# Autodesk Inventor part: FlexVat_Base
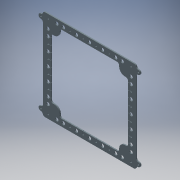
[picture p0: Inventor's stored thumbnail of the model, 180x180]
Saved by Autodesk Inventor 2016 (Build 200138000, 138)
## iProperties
Created: 2015-11
Part Number: FlexVat_Base
Material: Generic
Document SubType Name: Modeling
Designer: John
Density: 1 g/cm^3
Appearance: Default
Author: John
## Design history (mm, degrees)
feature "Base1"
node "Direct Edit1"
node "Direct Edit2"
fillet "Fillet1" dims "d24" = 5
sketch "Sketch1"
  geometry: L1 (-31.388, 174.618)-(-31.888, 174.618) reference; L2 (-31.388, -11.918)-(-31.888, -11.918) reference; L3 (-199.618, 156.308)-(-199.618, 155.81) reference; L4 (-199.618, 6.39)-(-199.618, 6.892) reference; L5 (-13.082, 6.392)-(-13.082, 6.892) reference; L6 (-180.808, 174.618)-(-181.308, 174.618) reference; L7 (-183.37, 169.575)-(-166.366, 169.575) reference; L8 (-166.366, 169.575)-(-166.366, 172.608) reference; L9 (-165.866, 172.608)-(-165.866, 169.575) reference; L10 (-165.866, 169.575)-(-151.424, 169.575) reference; L11 (-151.424, 169.575)-(-151.424, 174.618) reference; L12 (-150.924, 174.618)-(-150.924, 169.575) reference; L13 (-150.924, 169.575)-(-136.482, 169.575) reference; L14 (-136.482, 169.575)-(-136.482, 172.608) reference; L15 (-135.982, 172.608)-(-135.982, 169.575) reference; L16 (-135.982, 169.575)-(-121.54, 169.575) reference; L17 (-121.54, 169.575)-(-121.54, 174.618) reference; L18 (-121.04, 174.618)-(-121.04, 169.575) reference; L19 (-121.04, 169.575)-(-106.598, 169.575) reference; L20 (-106.598, 169.575)-(-106.598, 172.608) reference; L21 (-106.098, 172.608)-(-106.098, 169.575) reference; L22 (-106.098, 169.575)-(-91.656, 169.575) reference; L23 (-91.656, 169.575)-(-91.656, 174.618) reference; L24 (-91.156, 174.618)-(-91.156, 169.575) reference; L25 (-91.156, 169.575)-(-76.714, 169.575) reference; L26 (-76.714, 169.575)-(-76.714, 172.608) reference; L27 (-76.214, 172.608)-(-76.214, 169.575) reference; L28 (-76.214, 169.575)-(-61.772, 169.575) reference; L29 (-61.772, 169.575)-(-61.772, 174.618) reference; L30 (-61.272, 174.618)-(-61.272, 169.575) reference; L31 (-61.272, 169.575)-(-46.83, 169.575) reference; L32 (-46.83, 169.575)-(-46.83, 172.608) reference; L33 (-46.33, 172.608)-(-46.33, 169.575) reference; L34 (-46.33, 169.575)-(-29.33, 169.575) reference; L35 (-23.125, 154.794)-(-23.125, 141.366) reference; L36 (-23.125, 141.366)-(-15.092, 141.366) reference; L37 (-15.092, 140.87)-(-23.125, 140.87) reference; L38 (-23.125, 140.87)-(-23.125, 126.428) reference; L39 (-23.125, 126.428)-(-13.082, 126.428) reference; L40 (-13.082, 125.928)-(-23.125, 125.928) reference; L41 (-23.125, 125.928)-(-23.125, 111.482) reference; L42 (-15.092, 111.482)-(-23.125, 111.482) reference; L43 (-23.125, 110.986)-(-15.092, 110.986) reference; L44 (-23.125, 110.986)-(-23.125, 96.54) reference; L45 (-23.125, 96.54)-(-13.083, 96.54) reference; L46 (-13.081, 96.04)-(-23.125, 96.04) reference; L47 (-23.125, 96.04)-(-23.125, 81.602) reference; L48 (-23.125, 81.602)-(-15.092, 81.602) reference; L49 (-15.091, 81.098)-(-23.125, 81.098) reference; L50 (-23.125, 81.098)-(-23.125, 66.66) reference; L51 (-23.125, 66.66)-(-13.081, 66.66) reference; L52 (-13.082, 66.156)-(-23.125, 66.156) reference; L53 (-23.125, 66.156)-(-23.125, 51.718) reference; L54 (-15.091, 51.718)-(-23.125, 51.718) reference; L55 (-23.125, 51.214)-(-15.092, 51.214) reference; L56 (-23.125, 51.214)-(-23.125, 36.776) reference; L57 (-23.125, 36.776)-(-13.082, 36.776) reference; L58 (-13.082, 36.276)-(-23.125, 36.276) reference; L59 (-23.125, 36.276)-(-23.125, 21.834) reference; L60 (-15.092, 21.834)-(-23.125, 21.834) reference; L61 (-23.125, 21.33)-(-15.091, 21.33) reference; L62 (-23.125, 21.33)-(-23.125, 7.906) reference; L63 (-29.33, -6.875)-(-46.33, -6.875) reference; L64 (-46.33, -9.908)-(-46.33, -6.875) reference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; C1 r 1.75 at (-201, 176) reference; C2 r 1.75 at (-11.7, 171) reference; C3 r 1.75 at (-11.7, -13.3) reference; C4 r 1.75 at (-201, -13.3) reference; C5 r 1.75 at (-217.7, -10) reference; C6 r 1.75 at (-217.7, 172.7) reference; C7 r 1.75 at (5, 172.7) reference; C8 r 1.75 at (5, -10) reference; C9 r 8.125 at (-187.7, 0); C10 r 8.125 at (-187.7, 162.7); C11 r 8.125 at (-25, 162.7); C12 r 13.428 at (-25, 0); C13 r 13.428 at (-25, 162.7); C14 r 13.428 at (-187.7, 162.7); C15 r 13.428 at (-187.7, 0); A1 r 1.75 centre (-31.638, 176.35) between (-31.388, 174.618) and (-31.888, 174.618) reference; A2 r 1.75 centre (-31.638, -13.65) between (-31.888, -11.918) and (-31.388, -11.918) reference; A3 r 1.75 centre (-201.35, 156.058) between (-199.618, 156.308) and (-199.618, 155.81) reference; A4 r 1.75 centre (-201.35, 6.642) between (-199.618, 6.892) and (-199.618, 6.39) reference; A5 r 1.75 centre (-11.35, 6.642) between (-13.082, 6.392) and (-13.082, 6.892) reference; A6 r 1.75 centre (-181.058, 176.35) between (-180.808, 174.618) and (-181.308, 174.618) reference; A7 r 8.125 centre (-187.7, 162.7) between (-189.575, 154.794) and (-183.37, 169.575) reference; A8 r 3.75 centre (-166.116, 176.35) between (-165.866, 172.608) and (-166.366, 172.608) reference; A9 r 1.75 centre (-151.174, 176.35) between (-150.924, 174.618) and (-151.424, 174.618) reference; A10 r 3.75 centre (-136.232, 176.35) between (-135.982, 172.608) and (-136.482, 172.608) reference; A11 r 1.75 centre (-121.29, 176.35) between (-121.04, 174.618) and (-121.54, 174.618) reference; A12 r 3.75 centre (-106.348, 176.35) between (-106.098, 172.608) and (-106.598, 172.608) reference; A13 r 1.75 centre (-91.406, 176.35) between (-91.156, 174.618) and (-91.656, 174.618) reference; A14 r 3.75 centre (-76.464, 176.35) between (-76.214, 172.608) and (-76.714, 172.608) reference; A15 r 1.75 centre (-61.522, 176.35) between (-61.272, 174.618) and (-61.772, 174.618) reference; A16 r 3.75 centre (-46.58, 176.35) between (-46.33, 172.608) and (-46.83, 172.608) reference; A17 r 8.125 centre (-25, 162.7) between (-29.33, 169.575) and (-23.125, 154.794) reference; A18 r 3.75 centre (-11.35, 141.12) between (-15.092, 140.87) and (-15.092, 141.366) reference; A19 r 1.75 centre (-11.35, 126.178) between (-13.082, 125.928) and (-13.082, 126.428) reference; A20 r 3.75 centre (-11.35, 111.236) between (-15.092, 110.986) and (-15.092, 111.482) reference; A21 r 1.75 centre (-11.35, 96.294) between (-13.081, 96.04) and (-13.083, 96.54) reference; A22 r 3.75 centre (-11.35, 81.352) between (-15.091, 81.098) and (-15.092, 81.602) reference; A23 r 1.75 centre (-11.35, 66.406) between (-13.082, 66.156) and (-13.081, 66.66) reference; A24 r 3.75 centre (-11.35, 51.464) between (-15.092, 51.214) and (-15.091, 51.718) reference; A25 r 1.75 centre (-11.35, 36.526) between (-13.082, 36.276) and (-13.082, 36.776) reference; A26 r 3.75 centre (-11.35, 21.584) between (-15.091, 21.33) and (-15.092, 21.834) reference; A27 r 8.125 centre (-25, 0) between (-23.125, 7.906) and (-29.33, -6.875) reference; A28 r 3.75 centre (-46.58, -13.65) between (-46.83, -9.908) and (-46.33, -9.908) reference; A29 r 1.75 centre (-61.522, -13.65) between (-61.772, -11.918) and (-61.272, -11.918) reference; A30 r 3.75 centre (-76.464, -13.65) between (-76.714, -9.908) and (-76.214, -9.908) reference; A31 r 1.75 centre (-91.406, -13.65) between (-91.656, -11.918) and (-91.156, -11.918) reference; A32 r 3.75 centre (-106.348, -13.65) between (-106.598, -9.908) and (-106.098, -9.908) reference; A33 r 1.75 centre (-121.29, -13.65) between (-121.54, -11.918) and (-121.04, -11.918) reference; A34 r 3.75 centre (-136.232, -13.65) between (-136.482, -9.908) and (-135.982, -9.908) reference; A35 r 1.75 centre (-151.174, -13.65) between (-151.424, -11.918) and (-150.924, -11.918) reference; A36 r 3.75 centre (-166.116, -13.65) between (-166.366, -9.908) and (-165.866, -9.908) reference; A37 r 8.125 centre (-187.7, 0) between (-183.37, -6.875) and (-189.575, 7.906) reference; A38 r 3.75 centre (-201.35, 21.584) between (-197.608, 21.834) and (-197.609, 21.33) reference; A39 r 1.75 centre (-201.35, 36.522) between (-199.618, 36.772) and (-199.618, 36.272) reference; A40 r 3.75 centre (-201.35, 51.464) between (-197.609, 51.718) and (-197.608, 51.214) reference; A41 r 1.75 centre (-201.35, 66.406) between (-199.619, 66.66) and (-199.618, 66.156) reference; A42 r 3.75 centre (-201.35, 81.352) between (-197.608, 81.598) and (-197.609, 81.098) reference; A43 r 1.75 centre (-201.35, 96.29) between (-199.619, 96.544) and (-199.618, 96.04) reference; A44 r 3.75 centre (-201.35, 111.236) between (-197.608, 111.486) and (-197.609, 110.982) reference; A45 r 1.75 centre (-201.35, 126.178) between (-199.617, 126.424) and (-199.619, 125.924) reference; A46 r 3.75 centre (-201.35, 141.12) between (-197.608, 141.37) and (-197.609, 140.866) reference; A47 r 1.75 centre (-11.35, 156.058) between (-13.082, 155.809) and (-13.082, 156.308) reference; A48 r 1.75 centre (-181.058, -13.65) between (-181.308, -11.918) and (-180.808, -11.918) reference; A49 r 5 centre (-208.018, -17.5) between (-212.859, -18.75) and (-208.018, -22.5) reference; A50 r 5 centre (-4.682, -17.5) between (-4.682, -22.5) and (0.159, -18.75) reference; A51 r 5 centre (5, -20) between (5, -15) and (0.159, -18.75) reference; A52 r 5 centre (5, -10) between (5, -15) and (5, -5) reference; A53 r 5 centre (5, 0) between (0, 0) and (5, -5) reference; A54 r 5 centre (5, 162.7) between (5, 167.7) and (0, 162.7) reference; A55 r 5 centre (5, 172.7) between (5, 167.7) and (5, 177.7) reference; A56 r 5 centre (5, 182.7) between (0.159, 181.45) and (5, 177.7) reference; A57 r 5 centre (-4.682, 180.2) between (0.159, 181.45) and (-4.682, 185.2) reference; A58 r 5 centre (-208.018, 180.2) between (-208.018, 185.2) and (-212.859, 181.45) reference; A59 r 5 centre (-217.7, 182.7) between (-217.7, 177.7) and (-212.859, 181.45) reference; A60 r 5 centre (-217.7, 172.7) between (-217.7, 177.7) and (-217.7, 167.7) reference; A61 r 5 centre (-217.7, 162.7) between (-212.7, 162.7) and (-217.7, 167.7) reference; A62 r 5 centre (-217.7, 0) between (-217.7, -5) and (-212.7, 0) reference; A63 r 5 centre (-217.7, -10) between (-217.7, -5) and (-217.7, -15) reference; A64 r 5 centre (-217.7, -20) between (-212.859, -18.75) and (-217.7, -15) reference; 1 further point
  constraints: 7 centre point, 6 equal radius, 4 coincident, 1 tangent, 3 other
extrude "Extrusion1" join sketch "Sketch1" stored distance "d25" = 10; taper "d26" = 0 deg
sketch "Sketch2"
  geometry: L1 (-31.388, -11.918)-(-31.888, -11.918) reference; L2 (-4.682, -22.5)-(-208.018, -22.5) reference; L3 (0, 0)-(0, 162.7) reference; L4 (-208.018, 185.2)-(-4.682, 185.2) reference; L5 (-212.7, 0)-(-212.7, 162.7) reference; L6 (-180.808, -11.918)-(-181.308, -11.918) reference; L7 (-13.082, 155.809)-(-13.082, 156.308) reference; L8 (-180.808, 174.618)-(-181.308, 174.618) reference; L9 (-13.082, 6.392)-(-13.082, 6.892) reference; L10 (-199.618, 6.39)-(-199.618, 6.892) reference; L11 (-199.618, 156.308)-(-199.618, 155.81) reference; L12 (-31.388, 174.618)-(-31.888, 174.618) reference; L13 (-189.575, 13.297)-(-189.575, 21.33) reference; L14 (-197.609, 21.33)-(-189.575, 21.33) reference; L15 (-189.575, 21.834)-(-197.608, 21.834) reference; L16 (-189.575, 21.834)-(-189.575, 36.272) reference; L17 (-189.575, 36.272)-(-199.618, 36.272) reference; L18 (-199.618, 36.772)-(-189.575, 36.772) reference; L19 (-189.575, 36.772)-(-189.575, 51.214) reference; L20 (-189.575, 51.214)-(-197.608, 51.214) reference; L21 (-197.609, 51.718)-(-189.575, 51.718) reference; L22 (-189.575, 51.718)-(-189.575, 66.156) reference; L23 (-189.575, 66.156)-(-199.618, 66.156) reference; L24 (-199.619, 66.66)-(-189.575, 66.66) reference; L25 (-189.575, 66.66)-(-189.575, 81.098) reference; L26 (-197.609, 81.098)-(-189.575, 81.098) reference; L27 (-189.575, 81.598)-(-197.608, 81.598) reference; L28 (-189.575, 81.598)-(-189.575, 96.04) reference; L29 (-189.575, 96.04)-(-199.618, 96.04) reference; L30 (-199.619, 96.544)-(-189.575, 96.544) reference; L31 (-189.575, 96.544)-(-189.575, 110.982) reference; L32 (-197.609, 110.982)-(-189.575, 110.982) reference; L33 (-189.575, 111.486)-(-197.608, 111.486) reference; L34 (-189.575, 111.486)-(-189.575, 125.924) reference; L35 (-199.619, 125.924)-(-189.575, 125.924) reference; L36 (-189.575, 126.424)-(-199.617, 126.424) reference; L37 (-189.575, 126.424)-(-189.575, 140.866) reference; L38 (-197.609, 140.866)-(-189.575, 140.866) reference; L39 (-189.575, 141.37)-(-197.608, 141.37) reference; L40 (-189.575, 141.37)-(-189.575, 149.403) reference; L41 (-176.165, 169.575)-(-166.366, 169.575) reference; L42 (-166.366, 169.575)-(-166.366, 172.608) reference; L43 (-165.866, 172.608)-(-165.866, 169.575) reference; L44 (-165.866, 169.575)-(-151.424, 169.575) reference; L45 (-151.424, 169.575)-(-151.424, 174.618) reference; L46 (-150.924, 174.618)-(-150.924, 169.575) reference; L47 (-150.924, 169.575)-(-136.482, 169.575) reference; L48 (-136.482, 169.575)-(-136.482, 172.608) reference; L49 (-135.982, 172.608)-(-135.982, 169.575) reference; L50 (-135.982, 169.575)-(-121.54, 169.575) reference; L51 (-121.54, 169.575)-(-121.54, 174.618) reference; L52 (-121.04, 174.618)-(-121.04, 169.575) reference; L53 (-121.04, 169.575)-(-106.598, 169.575) reference; L54 (-106.598, 169.575)-(-106.598, 172.608) reference; L55 (-106.098, 172.608)-(-106.098, 169.575) reference; L56 (-106.098, 169.575)-(-91.656, 169.575) reference; L57 (-91.656, 169.575)-(-91.656, 174.618) reference; L58 (-91.156, 174.618)-(-91.156, 169.575) reference; L59 (-91.156, 169.575)-(-76.714, 169.575) reference; L60 (-76.714, 169.575)-(-76.714, 172.608) reference; L61 (-76.214, 172.608)-(-76.214, 169.575) reference; L62 (-76.214, 169.575)-(-61.772, 169.575) reference; L63 (-61.772, 169.575)-(-61.772, 174.618) reference; L64 (-61.272, 174.618)-(-61.272, 169.575) reference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; C1 r 1.75 at (5, -10) reference; C2 r 1.75 at (5, 172.7) reference; C3 r 1.75 at (-217.7, 172.7) reference; C4 r 1.75 at (-217.7, -10) reference; C5 r 1.75 at (-201, -13.3) reference; C6 r 1.75 at (-11.7, -13.3) reference; C7 r 1.75 at (-11.7, 171) reference; C8 r 1.75 at (-201, 176) reference; C9 r 3.75 at (-181.058, -13.65); C10 r 3.75 at (-201.35, 6.642); C11 r 3.75 at (-201.35, 156.058); C12 r 3.75 at (-181.058, 176.35); C13 r 3.75 at (-31.638, 176.35); C14 r 3.75 at (-11.35, 156.058); C15 r 3.75 at (-31.638, -13.65); C16 r 3.75 at (-11.35, 6.642); A1 r 1.75 centre (-31.638, -13.65) between (-31.888, -11.918) and (-31.388, -11.918) reference; A2 r 5 centre (-208.018, -17.5) between (-212.859, -18.75) and (-208.018, -22.5) reference; A3 r 5 centre (-4.682, -17.5) between (-4.682, -22.5) and (0.159, -18.75) reference; A4 r 5 centre (5, -20) between (5, -15) and (0.159, -18.75) reference; A5 r 5 centre (5, -10) between (5, -15) and (5, -5) reference; A6 r 5 centre (5, 0) between (0, 0) and (5, -5) reference; A7 r 5 centre (5, 162.7) between (5, 167.7) and (0, 162.7) reference; A8 r 5 centre (5, 172.7) between (5, 167.7) and (5, 177.7) reference; A9 r 5 centre (5, 182.7) between (0.159, 181.45) and (5, 177.7) reference; A10 r 5 centre (-4.682, 180.2) between (0.159, 181.45) and (-4.682, 185.2) reference; A11 r 5 centre (-208.018, 180.2) between (-208.018, 185.2) and (-212.859, 181.45) reference; A12 r 5 centre (-217.7, 182.7) between (-217.7, 177.7) and (-212.859, 181.45) reference; A13 r 5 centre (-217.7, 172.7) between (-217.7, 177.7) and (-217.7, 167.7) reference; A14 r 5 centre (-217.7, 162.7) between (-212.7, 162.7) and (-217.7, 167.7) reference; A15 r 5 centre (-217.7, 0) between (-217.7, -5) and (-212.7, 0) reference; A16 r 5 centre (-217.7, -10) between (-217.7, -5) and (-217.7, -15) reference; A17 r 5 centre (-217.7, -20) between (-212.859, -18.75) and (-217.7, -15) reference; A18 r 1.75 centre (-181.058, -13.65) between (-181.308, -11.918) and (-180.808, -11.918) reference; A19 r 1.75 centre (-11.35, 156.058) between (-13.082, 155.809) and (-13.082, 156.308) reference; A20 r 1.75 centre (-181.058, 176.35) between (-180.808, 174.618) and (-181.308, 174.618) reference; A21 r 1.75 centre (-11.35, 6.642) between (-13.082, 6.392) and (-13.082, 6.892) reference; A22 r 1.75 centre (-201.35, 6.642) between (-199.618, 6.892) and (-199.618, 6.39) reference; A23 r 1.75 centre (-201.35, 156.058) between (-199.618, 156.308) and (-199.618, 155.81) reference; A24 r 1.75 centre (-31.638, 176.35) between (-31.388, 174.618) and (-31.888, 174.618) reference; A25 r 13.428 centre (-187.7, 0) between (-176.165, -6.875) and (-189.575, 13.297) reference; A26 r 3.75 centre (-201.35, 21.584) between (-197.608, 21.834) and (-197.609, 21.33) reference; A27 r 1.75 centre (-201.35, 36.522) between (-199.618, 36.772) and (-199.618, 36.272) reference; A28 r 3.75 centre (-201.35, 51.464) between (-197.609, 51.718) and (-197.608, 51.214) reference; A29 r 1.75 centre (-201.35, 66.406) between (-199.619, 66.66) and (-199.618, 66.156) reference; A30 r 3.75 centre (-201.35, 81.352) between (-197.608, 81.598) and (-197.609, 81.098) reference; A31 r 1.75 centre (-201.35, 96.29) between (-199.619, 96.544) and (-199.618, 96.04) reference; A32 r 3.75 centre (-201.35, 111.236) between (-197.608, 111.486) and (-197.609, 110.982) reference; A33 r 1.75 centre (-201.35, 126.178) between (-199.617, 126.424) and (-199.619, 125.924) reference; A34 r 3.75 centre (-201.35, 141.12) between (-197.608, 141.37) and (-197.609, 140.866) reference; A35 r 13.428 centre (-187.7, 162.7) between (-189.575, 149.403) and (-176.165, 169.575) reference; A36 r 3.75 centre (-166.116, 176.35) between (-165.866, 172.608) and (-166.366, 172.608) reference; A37 r 1.75 centre (-151.174, 176.35) between (-150.924, 174.618) and (-151.424, 174.618) reference; A38 r 3.75 centre (-136.232, 176.35) between (-135.982, 172.608) and (-136.482, 172.608) reference; A39 r 1.75 centre (-121.29, 176.35) between (-121.04, 174.618) and (-121.54, 174.618) reference; A40 r 3.75 centre (-106.348, 176.35) between (-106.098, 172.608) and (-106.598, 172.608) reference; A41 r 1.75 centre (-91.406, 176.35) between (-91.156, 174.618) and (-91.656, 174.618) reference; A42 r 3.75 centre (-76.464, 176.35) between (-76.214, 172.608) and (-76.714, 172.608) reference; A43 r 1.75 centre (-61.522, 176.35) between (-61.272, 174.618) and (-61.772, 174.618) reference; A44 r 3.75 centre (-46.58, 176.35) between (-46.33, 172.608) and (-46.83, 172.608) reference; A45 r 13.428 centre (-25, 162.7) between (-36.535, 169.575) and (-23.125, 149.403) reference; A46 r 3.75 centre (-11.35, 141.12) between (-15.092, 140.87) and (-15.092, 141.366) reference; A47 r 1.75 centre (-11.35, 126.178) between (-13.082, 125.928) and (-13.082, 126.428) reference; A48 r 3.75 centre (-11.35, 111.236) between (-15.092, 110.986) and (-15.092, 111.482) reference; A49 r 1.75 centre (-11.35, 96.294) between (-13.081, 96.04) and (-13.083, 96.54) reference; A50 r 3.75 centre (-11.35, 81.352) between (-15.091, 81.098) and (-15.092, 81.602) reference; A51 r 1.75 centre (-11.35, 66.406) between (-13.082, 66.156) and (-13.081, 66.66) reference; A52 r 3.75 centre (-11.35, 51.464) between (-15.092, 51.214) and (-15.091, 51.718) reference; A53 r 1.75 centre (-11.35, 36.526) between (-13.082, 36.276) and (-13.082, 36.776) reference; A54 r 3.75 centre (-11.35, 21.584) between (-15.091, 21.33) and (-15.092, 21.834) reference; A55 r 13.428 centre (-25, 0) between (-23.125, 13.297) and (-36.535, -6.875) reference; A56 r 3.75 centre (-46.58, -13.65) between (-46.83, -9.908) and (-46.33, -9.908) reference; A57 r 1.75 centre (-61.522, -13.65) between (-61.772, -11.918) and (-61.272, -11.918) reference; A58 r 3.75 centre (-76.464, -13.65) between (-76.714, -9.908) and (-76.214, -9.908) reference; A59 r 1.75 centre (-91.406, -13.65) between (-91.656, -11.918) and (-91.156, -11.918) reference; A60 r 3.75 centre (-106.348, -13.65) between (-106.598, -9.908) and (-106.098, -9.908) reference; A61 r 1.75 centre (-121.29, -13.65) between (-121.54, -11.918) and (-121.04, -11.918) reference; A62 r 3.75 centre (-136.232, -13.65) between (-136.482, -9.908) and (-135.982, -9.908) reference; A63 r 1.75 centre (-151.174, -13.65) between (-151.424, -11.918) and (-150.924, -11.918) reference; A64 r 3.75 centre (-166.116, -13.65) between (-166.366, -9.908) and (-165.866, -9.908) reference; 1 further point
  constraints: 8 centre point, 8 coincident, 8 equal radius
extrude "Extrusion2" cut sketch "Sketch2" stored distance "d27" = 10; taper "d28" = 0 deg
node "Direct Edit3"
fillet "Fillet2" dims "d32" = 5
node "Direct Edit4"
node "Direct Edit5"
fillet "Fillet3" dims "d39" = 5
body "Solid1"
node "Projected Loop1"
node "Projected Loop2"
move_body "Move1" dims "d0" = 5
move_body "Move2" dims "d3" = -5
move_body "Move3" dims "d7" = 5
move_body "Move4" dims "d10" = -5
move_body "Move5" dims "d14" = -5
move_body "Move6" dims "d17" = -2.5
move_body "Move7" dims "d20" = -5
move_body "Move8" dims "d23" = 2.5
move_body "Move9" dims "d30" = -5
move_body "Move10" dims "d33" = -5
move_body "Move11" dims "d38" = -5
other parameters: "d1" = 0, "d2" = 0, "d4" = 0, "d5" = 0, "d6" = 0, "d8" = 0, "d9" = 0, "d11" = 0, "d12" = 0, "d13" = 0, "d15" = 0, "d16" = 0, "d18" = 0, "d19" = 0, "d21" = 0, "d22" = 0, "d29" = 0, "d31" = 0, "d34" = 0, "d35" = 0, "d36" = 0, "d37" = 0
